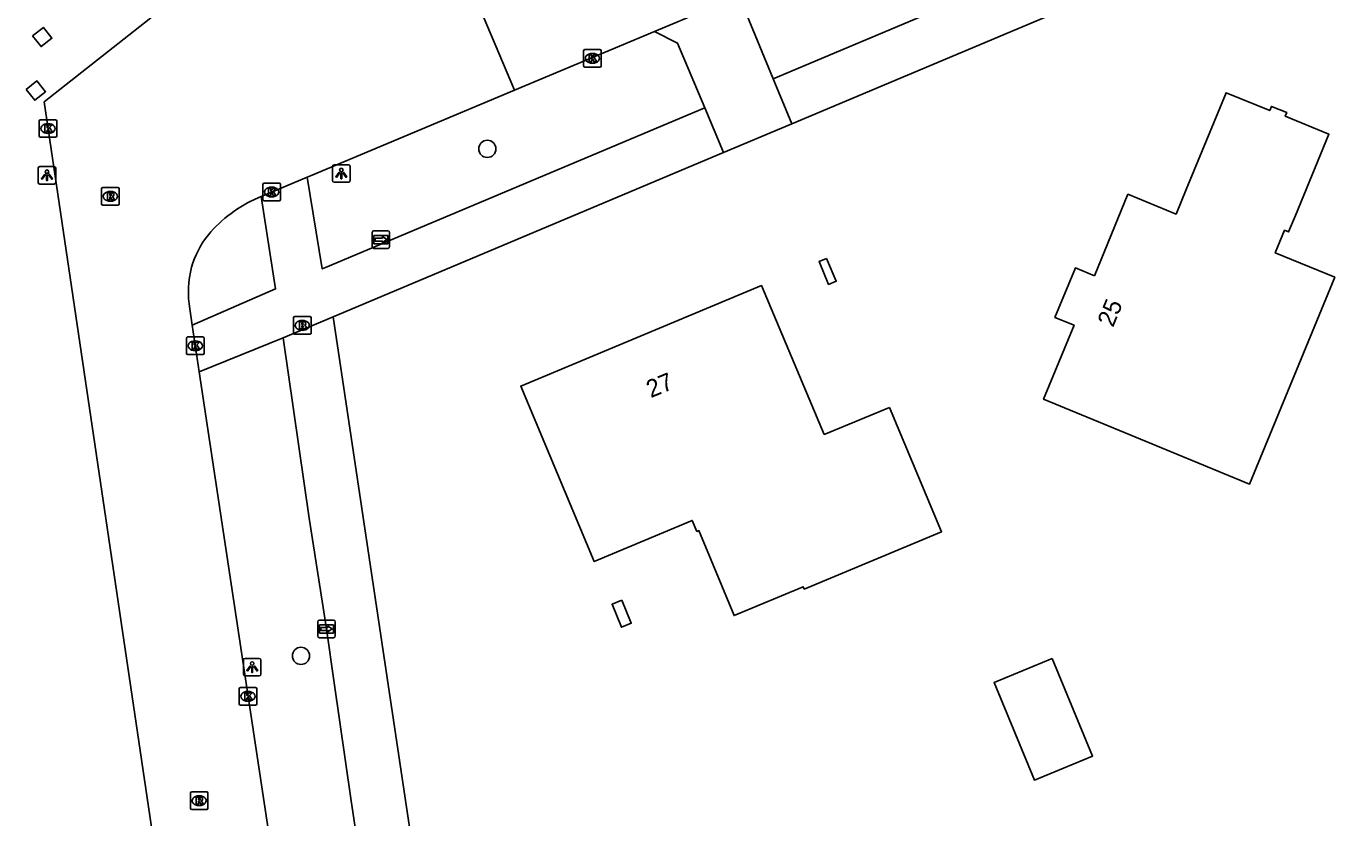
# Model space of a CAD drawing. Extents: x 162417 to 163721, y 384268 to 385416.
# Drawn here: x 163158.5 to 163232.9, y 384866.4 to 384911.4 of the extents above; entities that cross this region are included whole.
import ezdxf

# ---------------------------------------------------------------- set-up
doc = ezdxf.new("R2010")
doc.units = 0
for name, color, linetype in [('IMGEO_Boom', 7, 'Continuous'), ('IMGEO_Brandkraan', 7, 'Continuous'), ('IMGEO_Erf', 7, 'Continuous'), ('IMGEO_Kolk', 7, 'Continuous'), ('IMGEO_Lichtpunt', 7, 'Continuous'), ('IMGEO_Pand', 7, 'Continuous'), ('IMGEO_Pand_nummerreeks', 7, 'Continuous'), ('IMGEO_Rijbaan_lokaal_gesloten', 7, 'Continuous'), ('IMGEO_Rioolput', 7, 'Continuous'), ('IMGEO_Voetpad_open', 7, 'Continuous'), ('IMGEO_Wegwijzer', 7, 'Continuous')]:
    doc.layers.add(name, color=color, linetype=linetype)

msp = doc.modelspace()

# ---------------------------------------------------------------- linework, layer by layer
at = {"layer": 'IMGEO_Boom'}
for centre in [(163184.731, 384904.423), (163174.147, 384875.612)]:
    msp.add_circle(centre, 0.489, dxfattribs=at)
at = {"layer": 'IMGEO_Brandkraan'}
for p, q in [((163173.72, 384893.966), (163173.72, 384894.818)), ((163173.795, 384894.892), (163174.647, 384894.892)), ((163174.208, 384894.672), (163174.233, 384894.672)), ((163174.721, 384894.818), (163174.721, 384893.966)), ((163174.647, 384893.892), (163173.795, 384893.892)), ((163174.231, 384894.112), (163174.206, 384894.112))]:
    msp.add_line(p, q, dxfattribs=at)
for points in [[(163173.72, 384893.966), (163173.72, 384894.818)], [(163173.795, 384894.892), (163174.647, 384894.892)], [(163174.068, 384894.592), (163174.068, 384894.192), (163174.281, 384894.192)], [(163174.299, 384894.592), (163174.068, 384894.592)], [(163174.247, 384894.511), (163174.193, 384894.511), (163174.193, 384894.435)], [(163174.193, 384894.435), (163174.246, 384894.435)], [(163174.255, 384894.359), (163174.193, 384894.359), (163174.193, 384894.278)], [(163174.721, 384894.818), (163174.721, 384893.966)], [(163174.647, 384893.892), (163173.795, 384893.892)], [(163174.193, 384894.278), (163174.255, 384894.278)]]:
    msp.add_lwpolyline(points, dxfattribs=at)
for centre, radius, start, end in [((163173.797, 384894.816), 0.0765, 91.55205, 178.44795), ((163173.797, 384894.816), 0.0765, 91.55205, 178.44795), ((163174.248, 384894.473), 0.0379, 267.82845, 90.93552), ((163174.256, 384894.318), 0.0404, 269.87594, 90.50774), ((163174.303, 384894.447), 0.145, 59.4692, 91.53667), ((163174.328, 384894.494), 0.0922, 285.51372, 58.15012), ((163174.333, 384894.302), 0.105, 301.31148, 78.98903), ((163174.645, 384894.816), 0.0765, 1.55205, 88.44795), ((163174.645, 384894.816), 0.0765, 1.55205, 88.44795), ((163173.797, 384893.968), 0.0765, 181.55205, 268.44795), ((163173.797, 384893.968), 0.0765, 181.55205, 268.44795), ((163174.287, 384894.443), 0.251, 268.66757, 293.53466), ((163174.645, 384893.968), 0.0765, 271.55205, 358.44795), ((163174.645, 384893.968), 0.0765, 271.55205, 358.44795)]:
    msp.add_arc(centre, radius, start, end, dxfattribs=at)
for centre, major_axis, ratio, start_param, end_param in [((163174.207, 384894.392), (-0.387, 0.002), 0.722429, 4.712389, 7.853982), ((163174.232, 384894.392), (-0.39, 0.002), 0.717154, 1.570796, 4.712389)]:
    msp.add_ellipse(centre, major_axis=major_axis, ratio=ratio, start_param=start_param, end_param=end_param, dxfattribs=at)
at = {"layer": 'IMGEO_Erf'}
for points in [[(163158.908, 384910.853), (163159.521, 384911.33), (163160.001, 384910.711), (163159.388, 384910.235), (163158.908, 384910.853)], [(163158.541, 384907.796), (163159.149, 384908.282), (163159.639, 384907.669), (163159.031, 384907.183), (163158.541, 384907.796)]]:
    msp.add_lwpolyline(points, dxfattribs=at)
at = {"layer": 'IMGEO_Kolk'}
for p, q in [((163190.201, 384909.142), (163190.201, 384909.994)), ((163190.276, 384910.068), (163191.128, 384910.068)), ((163191.202, 384909.994), (163191.202, 384909.142)), ((163190.712, 384909.288), (163190.687, 384909.288)), ((163190.689, 384909.848), (163190.714, 384909.848)), ((163191.128, 384909.068), (163190.276, 384909.068)), ((163159.282, 384905.156), (163159.282, 384906.008)), ((163159.357, 384906.082), (163160.209, 384906.082)), ((163159.77, 384905.862), (163159.795, 384905.862)), ((163160.283, 384906.008), (163160.283, 384905.156)), ((163160.209, 384905.082), (163159.357, 384905.082)), ((163159.793, 384905.302), (163159.768, 384905.302)), ((163172.058, 384902.474), (163172.91, 384902.474)), ((163171.983, 384901.548), (163171.983, 384902.4)), ((163172.471, 384902.254), (163172.496, 384902.254)), ((163172.984, 384902.4), (163172.984, 384901.548)), ((163172.91, 384901.474), (163172.058, 384901.474)), ((163172.494, 384901.694), (163172.469, 384901.694)), ((163167.645, 384892.808), (163167.645, 384893.66)), ((163167.72, 384893.734), (163168.572, 384893.734)), ((163168.646, 384893.66), (163168.646, 384892.808)), ((163168.156, 384892.954), (163168.131, 384892.954)), ((163168.133, 384893.514), (163168.158, 384893.514)), ((163168.572, 384892.734), (163167.72, 384892.734)), ((163170.636, 384872.888), (163170.636, 384873.74)), ((163170.711, 384873.814), (163171.563, 384873.814)), ((163171.124, 384873.594), (163171.149, 384873.594)), ((163171.637, 384873.74), (163171.637, 384872.888)), ((163171.563, 384872.814), (163170.711, 384872.814)), ((163171.147, 384873.034), (163171.122, 384873.034))]:
    msp.add_line(p, q, dxfattribs=at)
for points in [[(163190.201, 384909.142), (163190.201, 384909.994)], [(163190.276, 384910.068), (163191.128, 384910.068)], [(163191.202, 384909.994), (163191.202, 384909.142)], [(163190.522, 384909.768), (163190.645, 384909.768), (163190.645, 384909.617), (163190.775, 384909.768), (163190.939, 384909.768), (163190.793, 384909.617), (163190.946, 384909.368), (163190.794, 384909.368), (163190.709, 384909.532), (163190.645, 384909.465), (163190.645, 384909.368), (163190.522, 384909.368), (163190.522, 384909.768)], [(163191.128, 384909.068), (163190.276, 384909.068)], [(163159.282, 384905.156), (163159.282, 384906.008)], [(163159.357, 384906.082), (163160.209, 384906.082)], [(163159.603, 384905.782), (163159.726, 384905.782), (163159.726, 384905.631), (163159.856, 384905.782), (163160.02, 384905.782), (163159.874, 384905.631), (163160.027, 384905.382), (163159.875, 384905.382), (163159.79, 384905.546), (163159.726, 384905.479), (163159.726, 384905.382), (163159.603, 384905.382), (163159.603, 384905.782)], [(163160.283, 384906.008), (163160.283, 384905.156)], [(163160.209, 384905.082), (163159.357, 384905.082)], [(163172.058, 384902.474), (163172.91, 384902.474)], [(163171.983, 384901.548), (163171.983, 384902.4)], [(163172.304, 384902.174), (163172.427, 384902.174), (163172.427, 384902.023), (163172.557, 384902.174), (163172.721, 384902.174), (163172.575, 384902.023), (163172.728, 384901.774), (163172.576, 384901.774), (163172.491, 384901.938), (163172.427, 384901.871), (163172.427, 384901.774), (163172.304, 384901.774), (163172.304, 384902.174)], [(163172.984, 384902.4), (163172.984, 384901.548)], [(163172.91, 384901.474), (163172.058, 384901.474)], [(163167.645, 384892.808), (163167.645, 384893.66)], [(163167.72, 384893.734), (163168.572, 384893.734)], [(163168.646, 384893.66), (163168.646, 384892.808)], [(163167.966, 384893.434), (163168.089, 384893.434), (163168.089, 384893.283), (163168.219, 384893.434), (163168.383, 384893.434), (163168.237, 384893.283), (163168.39, 384893.034), (163168.238, 384893.034), (163168.153, 384893.198), (163168.089, 384893.131), (163168.089, 384893.034), (163167.966, 384893.034), (163167.966, 384893.434)], [(163168.572, 384892.734), (163167.72, 384892.734)], [(163170.636, 384872.888), (163170.636, 384873.74)], [(163170.711, 384873.814), (163171.563, 384873.814)], [(163170.957, 384873.514), (163171.08, 384873.514), (163171.08, 384873.363), (163171.21, 384873.514), (163171.374, 384873.514), (163171.228, 384873.363), (163171.381, 384873.114), (163171.229, 384873.114), (163171.144, 384873.278), (163171.08, 384873.211), (163171.08, 384873.114), (163170.957, 384873.114), (163170.957, 384873.514)], [(163171.637, 384873.74), (163171.637, 384872.888)], [(163171.563, 384872.814), (163170.711, 384872.814)]]:
    msp.add_lwpolyline(points, dxfattribs=at)
for centre, start, end in [((163190.278, 384909.992), 91.55205, 178.44795), ((163190.278, 384909.992), 91.55205, 178.44795), ((163191.126, 384909.992), 1.55205, 88.44795), ((163191.126, 384909.992), 1.55205, 88.44795), ((163190.278, 384909.144), 181.55205, 268.44795), ((163190.278, 384909.144), 181.55205, 268.44795), ((163191.126, 384909.144), 271.55205, 358.44795), ((163191.126, 384909.144), 271.55205, 358.44795), ((163159.359, 384906.006), 91.55205, 178.44795), ((163159.359, 384906.006), 91.55205, 178.44795), ((163160.207, 384906.006), 1.55205, 88.44795), ((163160.207, 384906.006), 1.55205, 88.44795), ((163159.359, 384905.158), 181.55205, 268.44795), ((163159.359, 384905.158), 181.55205, 268.44795), ((163160.207, 384905.158), 271.55205, 358.44795), ((163160.207, 384905.158), 271.55205, 358.44795), ((163172.06, 384902.398), 91.55205, 178.44795), ((163172.06, 384902.398), 91.55205, 178.44795), ((163172.908, 384902.398), 1.55205, 88.44795), ((163172.908, 384902.398), 1.55205, 88.44795), ((163172.06, 384901.55), 181.55205, 268.44795), ((163172.06, 384901.55), 181.55205, 268.44795), ((163172.908, 384901.55), 271.55205, 358.44795), ((163172.908, 384901.55), 271.55205, 358.44795), ((163167.722, 384893.658), 91.55205, 178.44795), ((163167.722, 384893.658), 91.55205, 178.44795), ((163168.57, 384893.658), 1.55205, 88.44795), ((163168.57, 384893.658), 1.55205, 88.44795), ((163167.722, 384892.81), 181.55205, 268.44795), ((163167.722, 384892.81), 181.55205, 268.44795), ((163168.57, 384892.81), 271.55205, 358.44795), ((163168.57, 384892.81), 271.55205, 358.44795), ((163170.713, 384873.738), 91.55205, 178.44795), ((163170.713, 384873.738), 91.55205, 178.44795), ((163171.561, 384873.738), 1.55205, 88.44795), ((163171.561, 384873.738), 1.55205, 88.44795), ((163170.713, 384872.89), 181.55205, 268.44795), ((163170.713, 384872.89), 181.55205, 268.44795), ((163171.561, 384872.89), 271.55205, 358.44795), ((163171.561, 384872.89), 271.55205, 358.44795)]:
    msp.add_arc(centre, 0.0765, start, end, dxfattribs=at)
for centre, major_axis, ratio, start_param, end_param in [((163190.688, 384909.568), (-0.387, 0.002), 0.722429, 4.712389, 7.853982), ((163190.713, 384909.568), (-0.39, 0.002), 0.717154, 1.570796, 4.712389), ((163159.769, 384905.582), (-0.387, 0.002), 0.722429, 4.712389, 7.853982), ((163159.794, 384905.582), (-0.39, 0.002), 0.717154, 1.570796, 4.712389), ((163172.47, 384901.974), (-0.387, 0.002), 0.722429, 4.712389, 7.853982), ((163172.495, 384901.974), (-0.39, 0.002), 0.717154, 1.570796, 4.712389), ((163168.132, 384893.234), (-0.387, 0.002), 0.722429, 4.712389, 7.853982), ((163168.157, 384893.234), (-0.39, 0.002), 0.717154, 1.570796, 4.712389), ((163171.123, 384873.314), (-0.387, 0.002), 0.722429, 4.712389, 7.853982), ((163171.148, 384873.314), (-0.39, 0.002), 0.717154, 1.570796, 4.712389)]:
    msp.add_ellipse(centre, major_axis=major_axis, ratio=ratio, start_param=start_param, end_param=end_param, dxfattribs=at)
at = {"layer": 'IMGEO_Lichtpunt'}
for p, q in [((163159.223, 384903.327), (163159.223, 384902.52)), ((163159.223, 384903.327), (163159.223, 384902.52)), ((163160.125, 384903.422), (163159.317, 384903.422)), ((163160.125, 384903.422), (163159.317, 384903.422)), ((163160.219, 384902.52), (163160.219, 384903.327)), ((163160.219, 384902.52), (163160.219, 384903.327)), ((163175.939, 384903.43), (163175.939, 384902.623)), ((163175.939, 384903.43), (163175.939, 384902.623)), ((163176.841, 384903.525), (163176.033, 384903.525)), ((163176.841, 384903.525), (163176.033, 384903.525)), ((163176.935, 384902.623), (163176.935, 384903.43)), ((163176.935, 384902.623), (163176.935, 384903.43)), ((163176.033, 384902.529), (163176.841, 384902.529)), ((163176.033, 384902.529), (163176.841, 384902.529)), ((163159.317, 384902.426), (163160.125, 384902.426)), ((163159.317, 384902.426), (163160.125, 384902.426)), ((163170.879, 384875.377), (163170.879, 384874.57)), ((163170.879, 384875.377), (163170.879, 384874.57)), ((163171.781, 384875.472), (163170.973, 384875.472)), ((163171.781, 384875.472), (163170.973, 384875.472)), ((163171.875, 384874.57), (163171.875, 384875.377)), ((163171.875, 384874.57), (163171.875, 384875.377)), ((163170.973, 384874.476), (163171.781, 384874.476)), ((163170.973, 384874.476), (163171.781, 384874.476))]:
    msp.add_line(p, q, dxfattribs=at)
for points in [[(163159.597, 384902.991), (163159.636, 384902.963), (163159.448, 384902.701), (163159.41, 384902.728), (163159.597, 384902.991)], [(163159.699, 384902.943), (163159.746, 384902.943), (163159.746, 384902.621), (163159.699, 384902.621), (163159.699, 384902.943)], [(163159.809, 384902.963), (163159.847, 384902.99), (163160.034, 384902.728), (163159.995, 384902.7), (163159.809, 384902.963)], [(163176.313, 384903.094), (163176.352, 384903.066), (163176.164, 384902.804), (163176.126, 384902.831), (163176.313, 384903.094)], [(163176.415, 384903.046), (163176.462, 384903.046), (163176.462, 384902.724), (163176.415, 384902.724), (163176.415, 384903.046)], [(163176.525, 384903.066), (163176.563, 384903.093), (163176.75, 384902.831), (163176.711, 384902.803), (163176.525, 384903.066)], [(163171.253, 384875.041), (163171.292, 384875.013), (163171.104, 384874.751), (163171.066, 384874.778), (163171.253, 384875.041)], [(163171.355, 384874.993), (163171.402, 384874.993), (163171.402, 384874.671), (163171.355, 384874.671), (163171.355, 384874.993)], [(163171.465, 384875.013), (163171.503, 384875.04), (163171.69, 384874.778), (163171.651, 384874.75), (163171.465, 384875.013)]]:
    msp.add_lwpolyline(points, dxfattribs=at)
for centre in [(163159.722, 384903.125), (163176.438, 384903.228), (163171.378, 384875.175)]:
    msp.add_circle(centre, 0.0994, dxfattribs=at)
for centre, start, end in [((163159.317, 384903.327), 90, 180), ((163159.317, 384903.327), 90, 180), ((163160.125, 384903.327), 0, 90), ((163160.125, 384903.327), 0, 90), ((163176.033, 384903.43), 90, 180), ((163176.033, 384903.43), 90, 180), ((163176.841, 384903.43), 0, 90), ((163176.841, 384903.43), 0, 90), ((163159.317, 384902.52), 180, 270), ((163159.317, 384902.52), 180, 270), ((163160.125, 384902.52), 270, 0), ((163160.125, 384902.52), 270, 360), ((163176.033, 384902.623), 180, 270), ((163176.033, 384902.623), 180, 270), ((163176.841, 384902.623), 270, 0), ((163176.841, 384902.623), 270, 360), ((163170.973, 384875.377), 90, 180), ((163170.973, 384875.377), 90, 180), ((163171.781, 384875.377), 0, 90), ((163171.781, 384875.377), 0, 90), ((163170.973, 384874.57), 180, 270), ((163170.973, 384874.57), 180, 270), ((163171.781, 384874.57), 270, 0), ((163171.781, 384874.57), 270, 360)]:
    msp.add_arc(centre, 0.0946, start, end, dxfattribs=at)
at = {"layer": 'IMGEO_Pand'}
for points in [[(163219.212, 384897.218), (163221.117, 384901.842), (163223.845, 384900.717), (163224.418, 384902.108), (163226.688, 384907.618), (163229.166, 384906.596), (163229.267, 384906.841), (163230.138, 384906.482), (163230.053, 384906.278), (163232.528, 384905.258), (163230.623, 384900.636), (163230.24, 384899.706), (163230.013, 384899.799), (163229.485, 384898.518), (163232.864, 384897.126), (163228.023, 384885.379), (163220.95, 384888.293), (163216.327, 384890.198), (163218.057, 384894.399), (163216.97, 384894.847), (163218.13, 384897.663), (163219.212, 384897.218)], [(163204.002, 384898.194), (163204.551, 384896.897), (163204.113, 384896.72), (163203.576, 384898.018), (163204.002, 384898.194)], [(163207.571, 384889.719), (163210.531, 384882.668), (163202.73, 384879.41), (163202.676, 384879.54), (163198.744, 384877.898), (163196.747, 384882.732), (163196.636, 384882.685), (163196.371, 384883.306), (163190.802, 384880.971), (163186.632, 384890.943), (163200.299, 384896.652), (163203.868, 384888.194), (163207.571, 384889.719)], [(163192.363, 384878.77), (163192.905, 384877.463), (163192.36, 384877.237), (163191.817, 384878.544), (163192.363, 384878.77)], [(163216.811, 384875.464), (163219.102, 384869.919), (163215.802, 384868.554), (163213.511, 384874.1), (163216.811, 384875.464)]]:
    msp.add_lwpolyline(points, dxfattribs=at)
at = {"layer": 'IMGEO_Rijbaan_lokaal_gesloten'}
for points in [[(163172.668, 384818.516), (163159.564, 384907.094), (163168.293, 384913.998)], [(163183.667, 384913.961), (163186.272, 384907.759)], [(163194.231, 384911.102), (163200.018, 384913.546)], [(163186.272, 384907.759), (163194.231, 384911.102)], [(163186.272, 384907.759), (163174.684, 384902.892), (163174.507, 384902.818)], [(163174.507, 384902.818), (163172.075, 384901.798), (163171.894, 384901.719)], [(163171.894, 384901.719), (163171.712, 384901.639)], [(163167.833, 384895.326), (163167.974, 384894.412)], [(163167.974, 384894.412), (163168.375, 384891.762)], [(163168.375, 384891.762), (163181.052, 384807.665)]]:
    msp.add_lwpolyline(points, dxfattribs=at)
for centre, radius, start, end in [((163174.631, 384894.765), 7.468, 113.00878, 140.25543), ((163172.938, 384896.273), 5.202, 141.10387, 164.00436), ((163173.401, 384896.276), 5.649, 165.32083, 189.67709)]:
    msp.add_arc(centre, radius, start, end, dxfattribs=at)
at = {"layer": 'IMGEO_Rioolput'}
for p, q in [((163162.823, 384901.302), (163162.823, 384902.154)), ((163162.898, 384902.228), (163163.75, 384902.228)), ((163163.311, 384902.008), (163163.336, 384902.008)), ((163163.824, 384902.154), (163163.824, 384901.302)), ((163163.75, 384901.228), (163162.898, 384901.228)), ((163163.334, 384901.448), (163163.309, 384901.448)), ((163167.865, 384866.958), (163167.865, 384867.81)), ((163167.94, 384867.884), (163168.792, 384867.884)), ((163168.353, 384867.664), (163168.378, 384867.664)), ((163168.866, 384867.81), (163168.866, 384866.958)), ((163168.792, 384866.884), (163167.94, 384866.884)), ((163168.376, 384867.104), (163168.351, 384867.104))]:
    msp.add_line(p, q, dxfattribs=at)
for points in [[(163162.823, 384901.302), (163162.823, 384902.154)], [(163162.898, 384902.228), (163163.75, 384902.228)], [(163163.412, 384901.926), (163163.16, 384901.928), (163163.16, 384901.528)], [(163163.338, 384901.847), (163163.284, 384901.847), (163163.284, 384901.766)], [(163163.284, 384901.766), (163163.336, 384901.766)], [(163163.824, 384902.154), (163163.824, 384901.302)], [(163163.75, 384901.228), (163162.898, 384901.228)], [(163163.16, 384901.528), (163163.284, 384901.528), (163163.284, 384901.69), (163163.295, 384901.69)], [(163163.342, 384901.661), (163163.413, 384901.528), (163163.553, 384901.528), (163163.488, 384901.654)], [(163167.865, 384866.958), (163167.865, 384867.81)], [(163167.94, 384867.884), (163168.792, 384867.884)], [(163168.454, 384867.582), (163168.202, 384867.584), (163168.202, 384867.184)], [(163168.866, 384867.81), (163168.866, 384866.958)], [(163168.792, 384866.884), (163167.94, 384866.884)], [(163168.202, 384867.184), (163168.326, 384867.184), (163168.326, 384867.346), (163168.337, 384867.346)], [(163168.38, 384867.503), (163168.326, 384867.503), (163168.326, 384867.422)], [(163168.326, 384867.422), (163168.378, 384867.422)], [(163168.384, 384867.317), (163168.455, 384867.184), (163168.595, 384867.184), (163168.53, 384867.31)]]:
    msp.add_lwpolyline(points, dxfattribs=at)
for centre, radius, start, end in [((163162.9, 384902.152), 0.0765, 91.55205, 178.44795), ((163162.9, 384902.152), 0.0765, 91.55205, 178.44795), ((163163.32, 384901.955), 0.19, 274.7715, 282.96867), ((163163.344, 384901.751), 0.0964, 77.00612, 93.18647), ((163163.358, 384901.808), 0.0378, 276.66336, 79.67722), ((163163.411, 384901.816), 0.109, 350.36119, 89.41601), ((163163.409, 384901.816), 0.112, 277.58423, 350.98172), ((163163.748, 384902.152), 0.0765, 1.55205, 88.44795), ((163163.748, 384902.152), 0.0765, 1.55205, 88.44795), ((163162.9, 384901.304), 0.0765, 181.55205, 268.44795), ((163162.9, 384901.304), 0.0765, 181.55205, 268.44795), ((163163.294, 384901.637), 0.0533, 26.02933, 88.69889), ((163163.393, 384901.601), 0.108, 29.51342, 73.79051), ((163163.748, 384901.304), 0.0765, 271.55205, 358.44795), ((163163.748, 384901.304), 0.0765, 271.55205, 358.44795), ((163167.942, 384867.808), 0.0765, 91.55205, 178.44795), ((163167.942, 384867.808), 0.0765, 91.55205, 178.44795), ((163168.453, 384867.472), 0.109, 350.36119, 89.41601), ((163168.79, 384867.808), 0.0765, 1.55205, 88.44795), ((163168.79, 384867.808), 0.0765, 1.55205, 88.44795), ((163167.942, 384866.96), 0.0765, 181.55205, 268.44795), ((163167.942, 384866.96), 0.0765, 181.55205, 268.44795), ((163168.336, 384867.293), 0.0533, 26.02933, 88.69889), ((163168.362, 384867.611), 0.19, 274.7715, 282.96867), ((163168.386, 384867.407), 0.0964, 77.00612, 93.18647), ((163168.4, 384867.464), 0.0378, 276.66336, 79.67722), ((163168.451, 384867.472), 0.112, 277.58423, 350.98172), ((163168.435, 384867.257), 0.108, 29.51342, 73.79051), ((163168.79, 384866.96), 0.0765, 271.55205, 358.44795), ((163168.79, 384866.96), 0.0765, 271.55205, 358.44795)]:
    msp.add_arc(centre, radius, start, end, dxfattribs=at)
for centre, major_axis, ratio, start_param, end_param in [((163163.31, 384901.728), (-0.387, 0.002), 0.722429, 4.712389, 7.853982), ((163163.335, 384901.728), (-0.39, 0.002), 0.717154, 1.570796, 4.712389), ((163168.352, 384867.384), (-0.387, 0.002), 0.722429, 4.712389, 7.853982), ((163168.377, 384867.384), (-0.39, 0.002), 0.717154, 1.570796, 4.712389)]:
    msp.add_ellipse(centre, major_axis=major_axis, ratio=ratio, start_param=start_param, end_param=end_param, dxfattribs=at)
at = {"layer": 'IMGEO_Voetpad_open'}
for points in [[(163226.912, 384919.359), (163200.97, 384908.409)], [(163227.943, 384916.773), (163202.03, 384905.85)], [(163200.97, 384908.409), (163199.446, 384912.087), (163200.018, 384913.546)], [(163197.077, 384906.757), (163195.54, 384910.438), (163194.231, 384911.102)], [(163200.97, 384908.409), (163202.03, 384905.85)], [(163197.077, 384906.757), (163175.545, 384897.682), (163175.359, 384897.603), (163174.507, 384902.818)], [(163198.14, 384904.21), (163197.077, 384906.757)], [(163202.03, 384905.85), (163198.14, 384904.21)], [(163198.14, 384904.21), (163175.984, 384894.871)], [(163171.894, 384901.719), (163172.706, 384896.469), (163167.974, 384894.412)], [(163173.131, 384893.686), (163175.984, 384894.871)], [(163175.984, 384894.871), (163189.317, 384805.604)], [(163168.375, 384891.762), (163173.131, 384893.686)], [(163173.131, 384893.686), (163174.611, 384883.435), (163175.599, 384877.142), (163176.027, 384874.074), (163176.986, 384867.512), (163177.654, 384862.939), (163181.731, 384836.256), (163185.853, 384808.72), (163186.458, 384804.456)]]:
    msp.add_lwpolyline(points, dxfattribs=at)
at = {"layer": 'IMGEO_Wegwijzer'}
for p, q in [((163178.194, 384898.868), (163178.194, 384899.668)), ((163178.194, 384899.668), (163178.194, 384898.868)), ((163178.294, 384899.768), (163179.084, 384899.768)), ((163179.084, 384899.768), (163178.294, 384899.768)), ((163179.184, 384899.668), (163179.184, 384898.868)), ((163179.184, 384898.868), (163179.184, 384899.668)), ((163179.084, 384898.768), (163178.294, 384898.768)), ((163178.294, 384898.768), (163179.084, 384898.768)), ((163175.104, 384876.742), (163175.104, 384877.542)), ((163175.104, 384877.542), (163175.104, 384876.742)), ((163175.204, 384877.642), (163175.994, 384877.642)), ((163175.994, 384877.642), (163175.204, 384877.642)), ((163176.094, 384877.542), (163176.094, 384876.742)), ((163176.094, 384876.742), (163176.094, 384877.542)), ((163175.994, 384876.642), (163175.204, 384876.642)), ((163175.204, 384876.642), (163175.994, 384876.642))]:
    msp.add_line(p, q, dxfattribs=at)
for points in [[(163178.295, 384899.5), (163179.083, 384899.5), (163179.083, 384899.036), (163178.295, 384899.036), (163178.295, 384899.5)], [(163178.36, 384899.352), (163178.36, 384899.268), (163178.36, 384899.184), (163178.771, 384899.184), (163178.771, 384899.101), (163179.018, 384899.268), (163178.771, 384899.435), (163178.771, 384899.352), (163178.36, 384899.352)], [(163175.205, 384877.374), (163175.993, 384877.374), (163175.993, 384876.91), (163175.205, 384876.91), (163175.205, 384877.374)], [(163175.27, 384877.226), (163175.27, 384877.142), (163175.27, 384877.058), (163175.681, 384877.058), (163175.681, 384876.975), (163175.928, 384877.142), (163175.681, 384877.309), (163175.681, 384877.226), (163175.27, 384877.226)]]:
    msp.add_lwpolyline(points, dxfattribs=at)
for centre, start, end in [((163178.294, 384899.668), 90, 180), ((163178.294, 384899.668), 90, 180), ((163179.084, 384899.668), 0, 90), ((163179.084, 384899.668), 360, 90), ((163178.294, 384898.868), 180, 270), ((163178.294, 384898.868), 180, 270), ((163179.084, 384898.868), 270, 0), ((163179.084, 384898.868), 270, 0), ((163175.204, 384877.542), 90, 180), ((163175.204, 384877.542), 90, 180), ((163175.994, 384877.542), 0, 90), ((163175.994, 384877.542), 360, 90), ((163175.204, 384876.742), 180, 270), ((163175.204, 384876.742), 180, 270), ((163175.994, 384876.742), 270, 0), ((163175.994, 384876.742), 270, 0)]:
    msp.add_arc(centre, 0.1, start, end, dxfattribs=at)

# ---------------------------------------------------------------- texts
at = {"layer": 'IMGEO_Pand_nummerreeks'}
for s, rotation, p in [('25', 67.61168, (163220.267, 384894.241)), ('27', 22.35681, (163194.017, 384890.255))]:
    msp.add_text(s, height=1, rotation=rotation, dxfattribs=at).set_placement(p)

doc.saveas('drawing.dxf')
